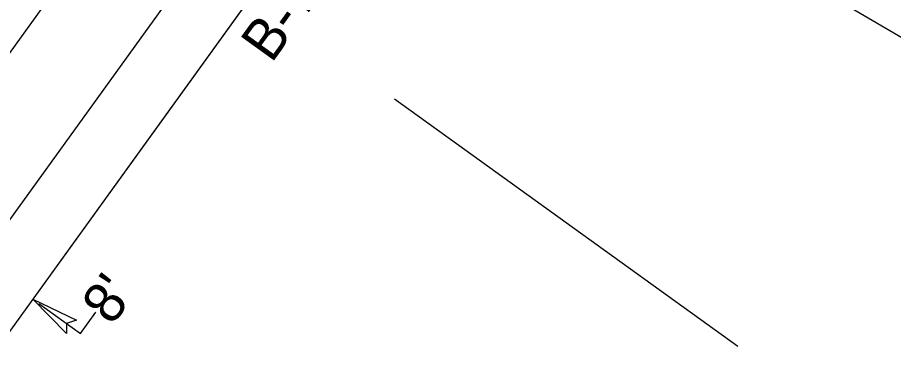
# Model space of a CAD drawing. Extents: x 2189281 to 2191267, y 386656 to 389012.
# Drawn here: x 2190394.2 to 2190501.9, y 387931.7 to 387975.4 of the extents above; entities that cross this region are included whole.
import ezdxf

# ---------------------------------------------------------------- set-up
doc = ezdxf.new("R2010")
doc.units = 0
for name, color, linetype in [('Prop Dimension', 7, 'Continuous'), ('Prop Dimension Text', 7, 'Continuous'), ('Prop DSN Text', 7, 'Continuous'), ('Prop EOT', 7, 'Continuous'), ('Prop Guardrail Anchor Unit CELL', 7, 'Continuous'), ('Prop Horizontal Alignment', 7, 'Continuous'), ('Prop Paved Shoulder', 7, 'Continuous'), ('Prop Roadway Bridge', 7, 'Continuous'), ('Prop Terminator CELL', 7, 'Continuous'), ('Scratch_Level_5', 7, 'Continuous')]:
    doc.layers.add(name, color=color, linetype=linetype)

msp = doc.modelspace()

# ---------------------------------------------------------------- linework, layer by layer
at = {"layer": 'Prop Dimension'}
for p, q in [((2190396.84, 387940.15), (2190401.95, 387936.46)), ((2190401.95, 387936.46), (2190403.84, 387939.08))]:
    msp.add_line(p, q, dxfattribs=at)
at = {"layer": 'Prop DSN Text'}
msp.add_lwpolyline([(2190687.03, 387855.75), (2190691.85, 387862.42), (2190426.76, 388017.45)], dxfattribs=at)
at = {"layer": 'Prop EOT'}
msp.add_lwpolyline([(2190181.76, 387658.83), (2190211.78, 387698.83), (2190504.24, 388104.37), (2190532.84, 388145.39)], dxfattribs=at)
at = {"layer": 'Prop Horizontal Alignment'}
msp.add_line((2189529.37, 386773.11), (2190699.23, 388395.27), dxfattribs=at)
at = {"layer": 'Prop Paved Shoulder'}
msp.add_line((2190443.46, 388006.42), (2190321.11, 387836.77), dxfattribs=at)
at = {"layer": 'Prop Roadway Bridge'}
msp.add_lwpolyline([(2190302.81, 387879.77), (2190396.4, 388009.54), (2190428.84, 387986.14), (2190335.25, 387856.37)], close=True, dxfattribs=at)
at = {"layer": 'Prop Terminator CELL'}
msp.add_lwpolyline([(2190400.23, 387936.46), (2190396.07, 387940.7), (2190401.45, 387938.11), (2190400.23, 387937.7)], close=True, dxfattribs=at)
at = {"layer": 'Scratch_Level_5'}
msp.add_line((2190440.58, 387965.34), (2190482.78, 387934.91), dxfattribs=at)

# ---------------------------------------------------------------- texts
at = {"layer": 'Prop Dimension Text'}
msp.add_text("8' ", height=5, rotation=54.2018, dxfattribs=at).set_placement((2190405.84, 387937.31))
at = {"layer": 'Prop Guardrail Anchor Unit CELL'}
msp.add_text('B-77', height=5, rotation=54.2018, dxfattribs=at).set_placement((2190425.43, 387969.62))

doc.saveas('drawing.dxf')
